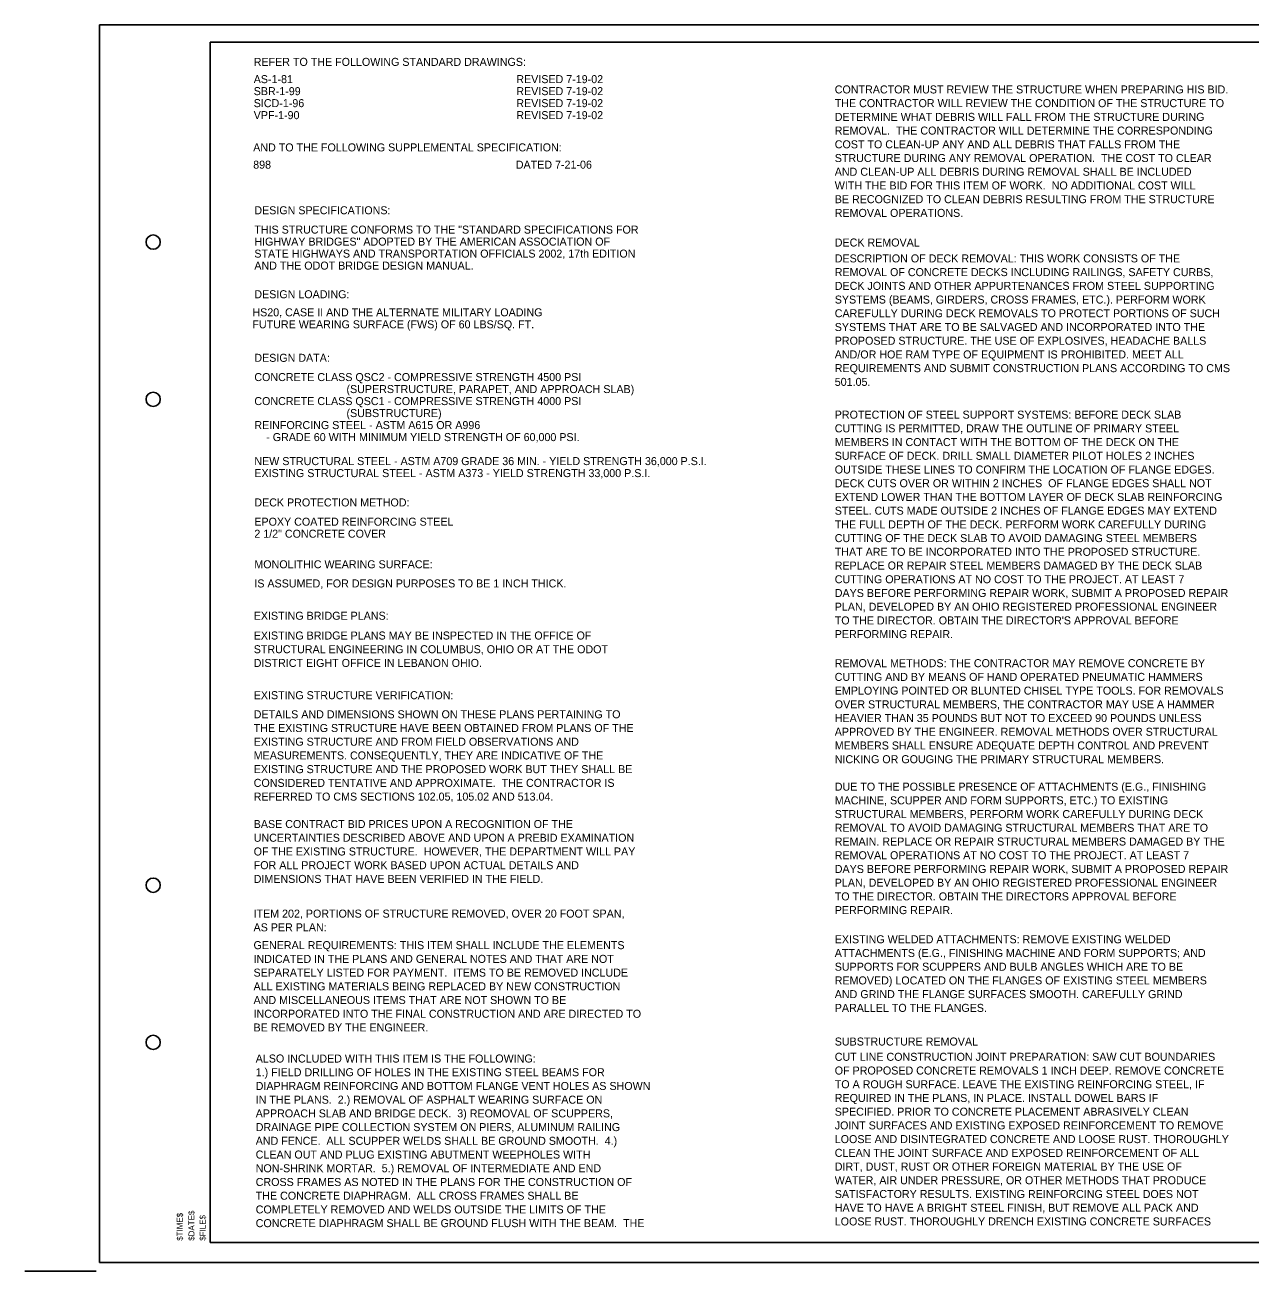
# Model space of a CAD drawing. Extents: x -70.8 to -34.9, y -11.3 to 10.7.
# Drawn here: x -70.82 to -49.38, y -11.27 to 10.53 of the extents above; entities that cross this region are included whole.
import ezdxf

# ---------------------------------------------------------------- set-up
doc = ezdxf.new("R2010")
doc.units = 0
for name, color, linetype in [('BR_P_Gen_Text', 7, 'Continuous'), ('Default', 7, 'Continuous'), ('SH_Border', 7, 'Continuous'), ('SH_Cut_Line', 7, 'Continuous')]:
    doc.layers.add(name, color=color, linetype=linetype)

msp = doc.modelspace()

# ---------------------------------------------------------------- linework, layer by layer
at = {"layer": 'SH_Border'}
msp.add_lwpolyline([(-67.571, 10.226), (-36.071, 10.226), (-36.071, -10.774), (-67.571, -10.774)], close=True, dxfattribs=at)
for centre in [(-68.571, 6.726), (-68.571, 3.976), (-68.571, -4.524), (-68.571, -7.274)]:
    msp.add_circle(centre, 0.125, dxfattribs=at)
at = {"layer": 'SH_Cut_Line'}
msp.add_line((-69.571, -11.274), (-70.815, -11.274), dxfattribs=at)
msp.add_lwpolyline([(-35.509, -11.124), (-69.509, -11.124), (-69.509, 10.526), (-35.509, 10.526)], close=True, dxfattribs=at)

# ---------------------------------------------------------------- texts
at = {"layer": 'BR_P_Gen_Text'}
for s, p in [('REFER TO THE FOLLOWING STANDARD DRAWINGS:', (-66.812, 9.809)), ('AS-1-81', (-66.812, 9.507)), ('REVISED 7-19-02', (-62.217, 9.507)), ('SBR-1-99', (-66.812, 9.297)), ('REVISED 7-19-02', (-62.217, 9.297)), ('CONTRACTOR MUST REVIEW THE STRUCTURE WHEN PREPARING HIS BID. ', (-56.645, 9.327)), ('SICD-1-96', (-66.812, 9.087)), ('REVISED 7-19-02', (-62.217, 9.087)), ('THE CONTRACTOR WILL REVIEW THE CONDITION OF THE STRUCTURE TO ', (-56.645, 9.087)), ('VPF-1-90', (-66.812, 8.877)), ('REVISED 7-19-02', (-62.217, 8.877)), ('DETERMINE WHAT DEBRIS WILL FALL FROM THE STRUCTURE DURING ', (-56.645, 8.847)), ('REMOVAL.  THE CONTRACTOR WILL DETERMINE THE CORRESPONDING ', (-56.645, 8.607)), ('COST TO CLEAN-UP ANY AND ALL DEBRIS THAT FALLS FROM THE ', (-56.645, 8.367)), ('STRUCTURE DURING ANY REMOVAL OPERATION.  THE COST TO CLEAR ', (-56.645, 8.127)), ('AND CLEAN-UP ALL DEBRIS DURING REMOVAL SHALL BE INCLUDED ', (-56.645, 7.887)), ('WITH THE BID FOR THIS ITEM OF WORK.  NO ADDITIONAL COST WILL ', (-56.645, 7.647)), ('BE RECOGNIZED TO CLEAN DEBRIS RESULTING FROM THE STRUCTURE ', (-56.645, 7.407)), ('DESIGN SPECIFICATIONS:', (-66.801, 7.213)), ('REMOVAL OPERATIONS.', (-56.645, 7.167)), ('THIS STRUCTURE CONFORMS TO THE "STANDARD SPECIFICATIONS FOR', (-66.801, 6.875)), ('HIGHWAY BRIDGES" ADOPTED BY THE AMERICAN ASSOCIATION OF ', (-66.801, 6.665)), ('DECK REMOVAL', (-56.645, 6.649)), ('STATE HIGHWAYS AND TRANSPORTATION OFFICIALS 2002, 17th EDITION', (-66.801, 6.455)), ('AND THE ODOT BRIDGE DESIGN MANUAL. ', (-66.801, 6.245)), ('DESCRIPTION OF DECK REMOVAL: THIS WORK CONSISTS OF THE ', (-56.645, 6.371)), ('REMOVAL OF CONCRETE DECKS INCLUDING RAILINGS, SAFETY CURBS, ', (-56.645, 6.131)), ('DECK JOINTS AND OTHER APPURTENANCES FROM STEEL SUPPORTING ', (-56.645, 5.891)), ('DESIGN LOADING:', (-66.801, 5.744)), ('SYSTEMS (BEAMS, GIRDERS, CROSS FRAMES, ETC.). PERFORM WORK ', (-56.645, 5.651)), ('HS20, CASE II AND THE ALTERNATE MILITARY LOADING', (-66.835, 5.428)), ('CAREFULLY DURING DECK REMOVALS TO PROTECT PORTIONS OF SUCH ', (-56.645, 5.411)), ('FUTURE WEARING SURFACE (FWS) OF 60 LBS/SQ. FT.', (-66.835, 5.218)), ('SYSTEMS THAT ARE TO BE SALVAGED AND INCORPORATED INTO THE ', (-56.645, 5.171)), ('PROPOSED STRUCTURE. THE USE OF EXPLOSIVES, HEADACHE BALLS ', (-56.645, 4.931)), ('AND/OR HOE RAM TYPE OF EQUIPMENT IS PROHIBITED. MEET ALL ', (-56.645, 4.691)), ('DESIGN DATA:', (-66.801, 4.632)), ('REQUIREMENTS AND SUBMIT CONSTRUCTION PLANS ACCORDING TO CMS ', (-56.645, 4.451)), ('CONCRETE CLASS QSC2 - COMPRESSIVE STRENGTH 4500 PSI', (-66.801, 4.295)), ('                               (SUPERSTRUCTURE, PARAPET, AND APPROACH SLAB)', (-66.801, 4.085)), ('501.05.', (-56.645, 4.211)), ('CONCRETE CLASS QSC1 - COMPRESSIVE STRENGTH 4000 PSI', (-66.801, 3.875)), ('                               (SUBSTRUCTURE)', (-66.801, 3.665)), ('PROTECTION OF STEEL SUPPORT SYSTEMS: BEFORE DECK SLAB ', (-56.645, 3.638)), ('REINFORCING STEEL - ASTM A615 OR A996', (-66.801, 3.455)), ('CUTTING IS PERMITTED, DRAW THE OUTLINE OF PRIMARY STEEL ', (-56.645, 3.398)), ('    - GRADE 60 WITH MINIMUM YIELD STRENGTH OF 60,000 PSI.', (-66.801, 3.245)), ('MEMBERS IN CONTACT WITH THE BOTTOM OF THE DECK ON THE ', (-56.645, 3.158)), ('SURFACE OF DECK. DRILL SMALL DIAMETER PILOT HOLES 2 INCHES ', (-56.645, 2.918)), ('NEW STRUCTURAL STEEL - ASTM A709 GRADE 36 MIN. - YIELD STRENGTH 36,000 P.S.I.', (-66.801, 2.825)), ('EXISTING STRUCTURAL STEEL - ASTM A373 - YIELD STRENGTH 33,000 P.S.I.', (-66.801, 2.615)), ('OUTSIDE THESE LINES TO CONFIRM THE LOCATION OF FLANGE EDGES. ', (-56.645, 2.678)), ('DECK CUTS OVER OR WITHIN 2 INCHES  OF FLANGE EDGES SHALL NOT ', (-56.645, 2.438)), ('DECK PROTECTION METHOD:', (-66.801, 2.102)), ('EXTEND LOWER THAN THE BOTTOM LAYER OF DECK SLAB REINFORCING ', (-56.645, 2.198)), ('STEEL. CUTS MADE OUTSIDE 2 INCHES OF FLANGE EDGES MAY EXTEND ', (-56.645, 1.958)), ('EPOXY COATED REINFORCING STEEL', (-66.801, 1.765)), ('THE FULL DEPTH OF THE DECK. PERFORM WORK CAREFULLY DURING ', (-56.645, 1.718)), ('2 1/2" CONCRETE COVER', (-66.801, 1.555)), ('CUTTING OF THE DECK SLAB TO AVOID DAMAGING STEEL MEMBERS ', (-56.645, 1.478)), ('THAT ARE TO BE INCORPORATED INTO THE PROPOSED STRUCTURE. ', (-56.645, 1.238)), ('MONOLITHIC WEARING SURFACE:', (-66.801, 1.02)), ('REPLACE OR REPAIR STEEL MEMBERS DAMAGED BY THE DECK SLAB ', (-56.645, 0.998)), ('CUTTING OPERATIONS AT NO COST TO THE PROJECT. AT LEAST 7 ', (-56.645, 0.758)), ('IS ASSUMED, FOR DESIGN PURPOSES TO BE 1 INCH THICK.', (-66.801, 0.685)), ('DAYS BEFORE PERFORMING REPAIR WORK, SUBMIT A PROPOSED REPAIR ', (-56.645, 0.518)), ('EXISTING BRIDGE PLANS:', (-66.812, 0.12)), ('PLAN, DEVELOPED BY AN OHIO REGISTERED PROFESSIONAL ENGINEER ', (-56.645, 0.278)), ("TO THE DIRECTOR. OBTAIN THE DIRECTOR'S APPROVAL BEFORE ", (-56.645, 0.038)), ('EXISTING BRIDGE PLANS MAY BE INSPECTED IN THE OFFICE OF ', (-66.812, -0.226)), ('PERFORMING REPAIR.', (-56.645, -0.202)), ('STRUCTURAL ENGINEERING IN COLUMBUS, OHIO OR AT THE ODOT ', (-66.812, -0.466)), ('DISTRICT EIGHT OFFICE IN LEBANON OHIO.', (-66.812, -0.706)), ('REMOVAL METHODS: THE CONTRACTOR MAY REMOVE CONCRETE BY ', (-56.645, -0.71)), ('CUTTING AND BY MEANS OF HAND OPERATED PNEUMATIC HAMMERS ', (-56.645, -0.95)), ('EMPLOYING POINTED OR BLUNTED CHISEL TYPE TOOLS. FOR REMOVALS ', (-56.645, -1.19)), ('EXISTING STRUCTURE VERIFICATION:', (-66.812, -1.27)), ('OVER STRUCTURAL MEMBERS, THE CONTRACTOR MAY USE A HAMMER ', (-56.645, -1.43)), ('DETAILS AND DIMENSIONS SHOWN ON THESE PLANS PERTAINING TO ', (-66.812, -1.604)), ('THE EXISTING STRUCTURE HAVE BEEN OBTAINED FROM PLANS OF THE ', (-66.812, -1.844)), ('HEAVIER THAN 35 POUNDS BUT NOT TO EXCEED 90 POUNDS UNLESS ', (-56.645, -1.67)), ('EXISTING STRUCTURE AND FROM FIELD OBSERVATIONS AND ', (-66.812, -2.084)), ('APPROVED BY THE ENGINEER. REMOVAL METHODS OVER STRUCTURAL ', (-56.645, -1.91)), ('MEMBERS SHALL ENSURE ADEQUATE DEPTH CONTROL AND PREVENT ', (-56.645, -2.15)), ('MEASUREMENTS. CONSEQUENTLY, THEY ARE INDICATIVE OF THE ', (-66.812, -2.324)), ('NICKING OR GOUGING THE PRIMARY STRUCTURAL MEMBERS.', (-56.645, -2.39)), ('EXISTING STRUCTURE AND THE PROPOSED WORK BUT THEY SHALL BE ', (-66.812, -2.564)), ('CONSIDERED TENTATIVE AND APPROXIMATE.  THE CONTRACTOR IS ', (-66.812, -2.804)), ('DUE TO THE POSSIBLE PRESENCE OF ATTACHMENTS (E.G., FINISHING ', (-56.645, -2.87)), ('REFERRED TO CMS SECTIONS 102.05, 105.02 AND 513.04.', (-66.812, -3.044)), ('MACHINE, SCUPPER AND FORM SUPPORTS, ETC.) TO EXISTING ', (-56.645, -3.11)), ('STRUCTURAL MEMBERS, PERFORM WORK CAREFULLY DURING DECK ', (-56.645, -3.35)), ('BASE CONTRACT BID PRICES UPON A RECOGNITION OF THE ', (-66.812, -3.524)), ('REMOVAL TO AVOID DAMAGING STRUCTURAL MEMBERS THAT ARE TO ', (-56.645, -3.59)), ('UNCERTAINTIES DESCRIBED ABOVE AND UPON A PREBID EXAMINATION ', (-66.812, -3.764)), ('REMAIN. REPLACE OR REPAIR STRUCTURAL MEMBERS DAMAGED BY THE ', (-56.645, -3.83)), ('OF THE EXISTING STRUCTURE.  HOWEVER, THE DEPARTMENT WILL PAY ', (-66.812, -4.004)), ('FOR ALL PROJECT WORK BASED UPON ACTUAL DETAILS AND ', (-66.812, -4.244)), ('REMOVAL OPERATIONS AT NO COST TO THE PROJECT. AT LEAST 7 ', (-56.645, -4.07)), ('DIMENSIONS THAT HAVE BEEN VERIFIED IN THE FIELD.', (-66.812, -4.484)), ('DAYS BEFORE PERFORMING REPAIR WORK, SUBMIT A PROPOSED REPAIR ', (-56.645, -4.31)), ('PLAN, DEVELOPED BY AN OHIO REGISTERED PROFESSIONAL ENGINEER ', (-56.645, -4.55)), ('TO THE DIRECTOR. OBTAIN THE DIRECTORS APPROVAL BEFORE ', (-56.645, -4.79)), ('ITEM 202, PORTIONS OF STRUCTURE REMOVED, OVER 20 FOOT SPAN,', (-66.815, -5.091)), ('PERFORMING REPAIR.', (-56.645, -5.03)), ('AS PER PLAN:', (-66.815, -5.331)), ('EXISTING WELDED ATTACHMENTS: REMOVE EXISTING WELDED ', (-56.645, -5.54)), ('GENERAL REQUIREMENTS: THIS ITEM SHALL INCLUDE THE ELEMENTS ', (-66.815, -5.643)), ('ATTACHMENTS (E.G., FINISHING MACHINE AND FORM SUPPORTS; AND ', (-56.645, -5.78)), ('INDICATED IN THE PLANS AND GENERAL NOTES AND THAT ARE NOT ', (-66.815, -5.883)), ('SUPPORTS FOR SCUPPERS AND BULB ANGLES WHICH ARE TO BE ', (-56.645, -6.02)), ('SEPARATELY LISTED FOR PAYMENT.  ITEMS TO BE REMOVED INCLUDE ', (-66.815, -6.123)), ('ALL EXISTING MATERIALS BEING REPLACED BY NEW CONSTRUCTION ', (-66.815, -6.363)), ('REMOVED) LOCATED ON THE FLANGES OF EXISTING STEEL MEMBERS ', (-56.645, -6.26)), ('AND MISCELLANEOUS ITEMS THAT ARE NOT SHOWN TO BE ', (-66.815, -6.603)), ('AND GRIND THE FLANGE SURFACES SMOOTH. CAREFULLY GRIND ', (-56.645, -6.5)), ('INCORPORATED INTO THE FINAL CONSTRUCTION AND ARE DIRECTED TO ', (-66.815, -6.843)), ('PARALLEL TO THE FLANGES.', (-56.645, -6.74)), ('BE REMOVED BY THE ENGINEER. ', (-66.815, -7.083)), ('SUBSTRUCTURE REMOVAL', (-56.645, -7.329)), ('ALSO INCLUDED WITH THIS ITEM IS THE FOLLOWING:', (-66.777, -7.626)), ('CUT LINE CONSTRUCTION JOINT PREPARATION: SAW CUT BOUNDARIES ', (-56.645, -7.596)), ('1.) FIELD DRILLING OF HOLES IN THE EXISTING STEEL BEAMS FOR ', (-66.777, -7.866)), ('OF PROPOSED CONCRETE REMOVALS 1 INCH DEEP. REMOVE CONCRETE ', (-56.645, -7.836)), ('DIAPHRAGM REINFORCING AND BOTTOM FLANGE VENT HOLES AS SHOWN ', (-66.777, -8.106)), ('TO A ROUGH SURFACE. LEAVE THE EXISTING REINFORCING STEEL, IF ', (-56.645, -8.076)), ('IN THE PLANS.  2.) REMOVAL OF ASPHALT WEARING SURFACE ON ', (-66.777, -8.346)), ('REQUIRED IN THE PLANS, IN PLACE. INSTALL DOWEL BARS IF ', (-56.645, -8.316)), ('APPROACH SLAB AND BRIDGE DECK.  3) REOMOVAL OF SCUPPERS, ', (-66.777, -8.586)), ('SPECIFIED. PRIOR TO CONCRETE PLACEMENT ABRASIVELY CLEAN ', (-56.645, -8.556)), ('DRAINAGE PIPE COLLECTION SYSTEM ON PIERS, ALUMINUM RAILING ', (-66.777, -8.826)), ('JOINT SURFACES AND EXISTING EXPOSED REINFORCEMENT TO REMOVE ', (-56.645, -8.796)), ('AND FENCE.  ALL SCUPPER WELDS SHALL BE GROUND SMOOTH.  4.) ', (-66.777, -9.066)), ('LOOSE AND DISINTEGRATED CONCRETE AND LOOSE RUST. THOROUGHLY ', (-56.645, -9.036)), ('CLEAN THE JOINT SURFACE AND EXPOSED REINFORCEMENT OF ALL ', (-56.645, -9.276)), ('CLEAN OUT AND PLUG EXISTING ABUTMENT WEEPHOLES WITH ', (-66.777, -9.306)), ('DIRT, DUST, RUST OR OTHER FOREIGN MATERIAL BY THE USE OF ', (-56.645, -9.516)), ('NON-SHRINK MORTAR.  5.) REMOVAL OF INTERMEDIATE AND END ', (-66.777, -9.546)), ('CROSS FRAMES AS NOTED IN THE PLANS FOR THE CONSTRUCTION OF ', (-66.777, -9.786)), ('WATER, AIR UNDER PRESSURE, OR OTHER METHODS THAT PRODUCE ', (-56.645, -9.756)), ('THE CONCRETE DIAPHRAGM.  ALL CROSS FRAMES SHALL BE ', (-66.777, -10.026)), ('SATISFACTORY RESULTS. EXISTING REINFORCING STEEL DOES NOT ', (-56.645, -9.996)), ('COMPLETELY REMOVED AND WELDS OUTSIDE THE LIMITS OF THE ', (-66.777, -10.266)), ('HAVE TO HAVE A BRIGHT STEEL FINISH, BUT REMOVE ALL PACK AND ', (-56.645, -10.236)), ('CONCRETE DIAPHRAGM SHALL BE GROUND FLUSH WITH THE BEAM.  THE', (-66.777, -10.506)), ('LOOSE RUST. THOROUGHLY DRENCH EXISTING CONCRETE SURFACES', (-56.645, -10.476))]:
    msp.add_text(s, height=0.14, dxfattribs=at).set_placement(p)
at = {"layer": 'Default'}
for s, p in [('AND TO THE FOLLOWING SUPPLEMENTAL SPECIFICATION:', (-66.821, 8.313)), ('898', (-66.821, 8.011)), ('DATED 7-21-06', (-62.226, 8.011))]:
    msp.add_text(s, height=0.14, dxfattribs=at).set_placement(p)
for s, p in [('$DATE$', (-67.849, -10.744)), ('$TIME$', (-68.053, -10.744)), ('$FILE$', (-67.654, -10.744))]:
    msp.add_text(s, height=0.1043, rotation=90.0067, dxfattribs=at).set_placement(p)

doc.saveas('drawing.dxf')
